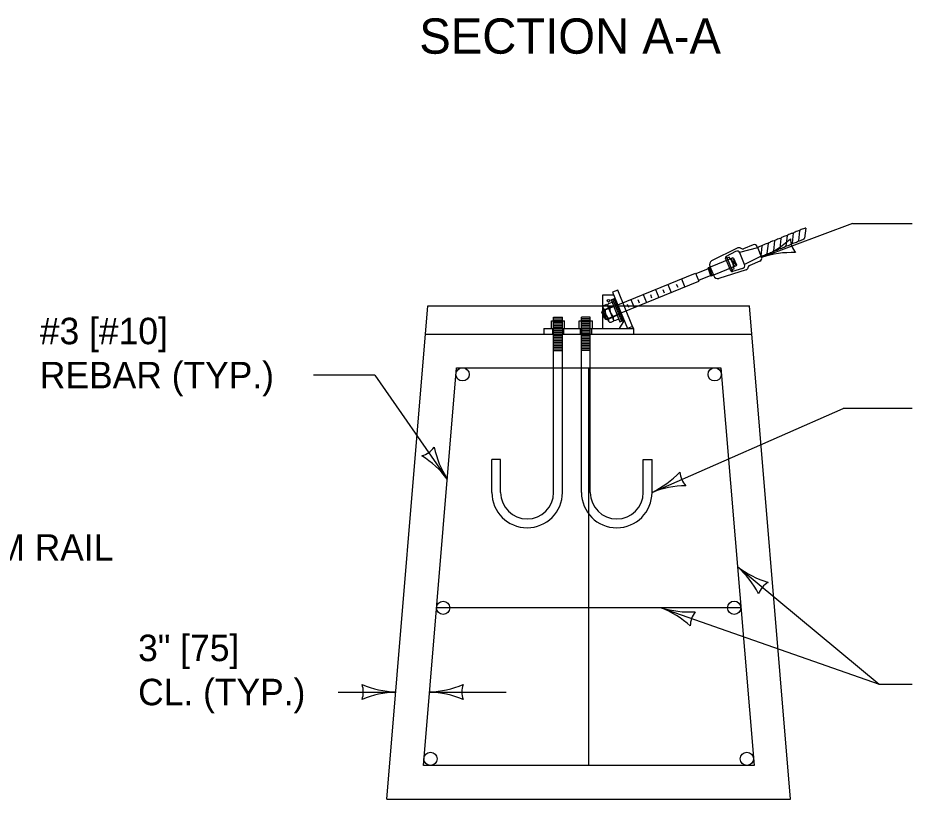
# Model space of a CAD drawing. Extents: x 49991.4 to 50021, y 49987.6 to 50011.4.
# Drawn here: x 50005.459 to 50007.485, y 49991.289 to 49993.059 of the extents above; entities that cross this region are included whole.
import ezdxf

# ---------------------------------------------------------------- set-up
doc = ezdxf.new("R2010")
doc.units = 0
for name, color, linetype in [('Level 1', 7, 'Continuous'), ('Level 2', 7, 'Continuous'), ('Level 3', 7, 'Continuous'), ('Level 4', 7, 'Continuous'), ('Level 7', 7, 'Continuous')]:
    doc.layers.add(name, color=color, linetype=linetype)

msp = doc.modelspace()

# ---------------------------------------------------------------- linework, layer by layer
at = {"layer": 'Level 1'}
for p, q in [((50007.2437, 49992.5827), (50007.2413, 49992.56)), ((50007.1874, 49992.5595), (50007.1849, 49992.537)), ((50007.1874, 49992.5595), (50007.1875, 49992.5596)), ((50007.2016, 49992.5653), (50007.199, 49992.5427)), ((50007.2157, 49992.5711), (50007.2131, 49992.5485)), ((50007.2298, 49992.5768), (50007.2272, 49992.5542)), ((50007.0888, 49992.5374), (50007.0305, 49992.5085)), ((50007.0955, 49992.5379), (50007.1, 49992.536)), ((50007.125, 49992.545), (50007.1025, 49992.5358)), ((50007.1337, 49992.5413), (50007.1437, 49992.5166)), ((50007.1426, 49992.5195), (50007.1451, 49992.5425)), ((50007.1567, 49992.5255), (50007.1592, 49992.5482)), ((50007.1733, 49992.5539), (50007.1708, 49992.5312)), ((50007.0849, 49992.5299), (50007.0639, 49992.5187)), ((50007.0707, 49992.517), (50007.0653, 49992.5148)), ((50007.105, 49992.5002), (50007.0943, 49992.5266)), ((50007.0647, 49992.5162), (50007.0622, 49992.5152)), ((50007.0738, 49992.4864), (50007.0624, 49992.5145)), ((50007.0647, 49992.5162), (50007.077, 49992.4868)), ((50007.0786, 49992.5156), (50007.0732, 49992.5134)), ((50007.0749, 49992.5141), (50007.0826, 49992.496)), ((50007.0784, 49992.5155), (50007.0861, 49992.4974)), ((50007.0802, 49992.5149), (50007.0786, 49992.5156)), ((50007.0786, 49992.5092), (50007.0817, 49992.502)), ((50007.0802, 49992.5149), (50007.0867, 49992.4996)), ((50007.0863, 49992.4975), (50007.0809, 49992.4953)), ((50007.0867, 49992.4996), (50007.0863, 49992.4975)), ((50007.1401, 49992.5079), (50007.1175, 49992.4984)), ((50006.8179, 49992.4091), (50006.9939, 49992.4808)), ((50006.9939, 49992.4808), (50007.0015, 49992.4623)), ((50007.0226, 49992.4908), (50006.9946, 49992.4791)), ((50007.0272, 49992.4947), (50007.0219, 49992.4925)), ((50007.0219, 49992.4925), (50007.0291, 49992.4742)), ((50007.0319, 49992.4753), (50007.0247, 49992.4937)), ((50007.0258, 49992.4866), (50007.0281, 49992.481)), ((50007.0266, 49992.4962), (50007.0355, 49992.4746)), ((50007.0288, 49992.4878), (50007.0311, 49992.4822)), ((50007.0347, 49992.4765), (50007.0291, 49992.4742)), ((50007.1085, 49992.4882), (50007.0468, 49992.4686)), ((50007.077, 49992.4868), (50007.0742, 49992.4856)), ((50007.0818, 49992.4904), (50007.0764, 49992.4882)), ((50007.1007, 49992.4912), (50007.0779, 49992.4845)), ((50007.1136, 49992.4949), (50007.1118, 49992.4906)), ((50006.8255, 49992.3905), (50007.0015, 49992.4623)), ((50006.9506, 49992.4559), (50006.9537, 49992.449)), ((50006.9621, 49992.4678), (50006.9696, 49992.4493)), ((50007.0287, 49992.4753), (50007.0008, 49992.4639)), ((50006.818, 49992.4426), (50006.8062, 49992.4378)), ((50006.8062, 49992.4378), (50006.8398, 49992.3554)), ((50006.8516, 49992.3602), (50006.818, 49992.4426)), ((50006.9037, 49992.444), (50006.9112, 49992.4255)), ((50006.9198, 49992.4437), (50006.9228, 49992.4364)), ((50006.9315, 49992.4553), (50006.9393, 49992.4369)), ((50006.7838, 49992.4314), (50006.8088, 49992.4314)), ((50006.7838, 49992.3953), (50006.7838, 49992.4314)), ((50006.8029, 49992.4203), (50006.8117, 49992.4244)), ((50006.8029, 49992.4203), (50006.8227, 49992.3707)), ((50006.806, 49992.4217), (50006.8262, 49992.372)), ((50006.8087, 49992.423), (50006.8293, 49992.3731)), ((50006.8478, 49992.4213), (50006.8554, 49992.4027)), ((50006.8637, 49992.4208), (50006.8668, 49992.4139)), ((50006.8756, 49992.4326), (50006.8831, 49992.414)), ((50006.8918, 49992.4323), (50006.8947, 49992.425)), ((50006.2946, 49991.2887), (50006.3877, 49992.4067)), ((50006.3877, 49992.4067), (50006.7855, 49992.4067)), ((50006.7821, 49992.3923), (50006.7832, 49992.3951)), ((50006.7832, 49992.3951), (50006.7869, 49992.3966)), ((50006.7915, 49992.3758), (50006.7838, 49992.3953)), ((50006.7971, 49992.3723), (50006.7846, 49992.4019)), ((50006.7871, 49992.4078), (50006.7935, 49992.4105)), ((50006.7906, 49992.3994), (50006.797, 49992.4021)), ((50006.7935, 49992.4105), (50006.8093, 49992.3724)), ((50006.7977, 49992.4122), (50006.805, 49992.4152)), ((50006.8012, 49992.4038), (50006.8083, 49992.4068)), ((50006.8394, 49992.4106), (50006.8421, 49992.4039)), ((50006.865, 49992.4067), (50007.1164, 49992.4067)), ((50007.2096, 49991.2887), (50007.1164, 49992.4067)), ((50006.6726, 49992.3808), (50006.6926, 49992.3808)), ((50006.6726, 49992.3554), (50006.6726, 49992.3808)), ((50006.6726, 49992.377), (50006.6926, 49992.377)), ((50006.6926, 49992.3554), (50006.6926, 49992.3808)), ((50006.7556, 49992.3808), (50006.7356, 49992.3808)), ((50006.7356, 49992.3554), (50006.7356, 49992.3808)), ((50006.7556, 49992.377), (50006.7356, 49992.377)), ((50006.7556, 49992.3554), (50006.7556, 49992.3808)), ((50006.7883, 49992.3771), (50006.7821, 49992.3923)), ((50006.7838, 49992.3554), (50006.7838, 49992.388)), ((50006.7887, 49992.3802), (50006.7843, 49992.3899)), ((50006.7913, 49992.381), (50006.7875, 49992.3909)), ((50006.7883, 49992.3771), (50006.7915, 49992.3758)), ((50006.7915, 49992.3758), (50006.795, 49992.3773)), ((50006.7996, 49992.3782), (50006.8058, 49992.3808)), ((50006.81, 49992.3825), (50006.8169, 49992.3854)), ((50006.8135, 49992.3741), (50006.8203, 49992.3769)), ((50006.6506, 49992.3554), (50006.8536, 49992.3554)), ((50006.6506, 49992.3554), (50006.6506, 49992.3427)), ((50006.6676, 49992.3554), (50006.6676, 49992.3724)), ((50006.6676, 49992.3724), (50006.6976, 49992.3724)), ((50006.6726, 49992.3733), (50006.6926, 49992.3733)), ((50006.6976, 49992.3554), (50006.6976, 49992.3724)), ((50006.7306, 49992.3554), (50006.7306, 49992.3724)), ((50006.7306, 49992.3724), (50006.7606, 49992.3724)), ((50006.7556, 49992.3733), (50006.7356, 49992.3733)), ((50006.7606, 49992.3554), (50006.7606, 49992.3724)), ((50006.803, 49992.3698), (50006.8093, 49992.3724)), ((50006.8218, 49992.3554), (50006.8327, 49992.373)), ((50006.8227, 49992.3707), (50006.8322, 49992.3742)), ((50006.8516, 49992.3602), (50006.8398, 49992.3554)), ((50006.8536, 49992.3554), (50006.8536, 49992.3427)), ((50006.3824, 49992.3427), (50007.1217, 49992.3427)), ((50006.6506, 49992.3427), (50006.8536, 49992.3427)), ((50006.6726, 49991.9838), (50006.6726, 49992.3427)), ((50006.6726, 49992.3395), (50006.6926, 49992.3395)), ((50006.6726, 49992.3358), (50006.6926, 49992.3358)), ((50006.6926, 49991.9838), (50006.6926, 49992.3427)), ((50006.7356, 49991.9838), (50006.7356, 49992.3427)), ((50006.7556, 49992.3395), (50006.7356, 49992.3395)), ((50006.7556, 49992.3358), (50006.7356, 49992.3358)), ((50006.7556, 49991.9838), (50006.7556, 49992.3427)), ((50006.6726, 49992.332), (50006.6926, 49992.332)), ((50006.6726, 49992.3283), (50006.6926, 49992.3283)), ((50006.6726, 49992.3245), (50006.6926, 49992.3245)), ((50006.6726, 49992.3208), (50006.6926, 49992.3208)), ((50006.6726, 49992.317), (50006.6926, 49992.317)), ((50006.7556, 49992.332), (50006.7356, 49992.332)), ((50006.7556, 49992.3283), (50006.7356, 49992.3283)), ((50006.7556, 49992.3245), (50006.7356, 49992.3245)), ((50006.7556, 49992.3208), (50006.7356, 49992.3208)), ((50006.7556, 49992.317), (50006.7356, 49992.317)), ((50006.6726, 49992.3133), (50006.6926, 49992.3133)), ((50006.6726, 49992.3095), (50006.6926, 49992.3095)), ((50006.6726, 49992.3058), (50006.6926, 49992.3058)), ((50006.7556, 49992.3133), (50006.7356, 49992.3133)), ((50006.7556, 49992.3095), (50006.7356, 49992.3095)), ((50006.7556, 49992.3058), (50006.7356, 49992.3058)), ((50006.3774, 49991.3649), (50006.4525, 49992.2664)), ((50006.4525, 49992.2664), (50007.0516, 49992.2664)), ((50006.7521, 49991.3649), (50006.7521, 49992.2664)), ((50007.0516, 49992.2664), (50007.1267, 49991.3649)), ((50006.5326, 49991.9838), (50006.5326, 49992.0588)), ((50006.5526, 49992.0588), (50006.5326, 49992.0588)), ((50006.5526, 49991.9838), (50006.5526, 49992.0588)), ((50006.8756, 49991.9838), (50006.8756, 49992.0588)), ((50006.8756, 49992.0588), (50006.8956, 49992.0588)), ((50006.8956, 49991.9838), (50006.8956, 49992.0588)), ((50007.0969, 49991.7224), (50006.4072, 49991.7224)), ((50007.1267, 49991.3649), (50006.3774, 49991.3649)), ((50006.2946, 49991.2887), (50007.2096, 49991.2887))]:
    msp.add_line(p, q, dxfattribs=at)
msp.add_circle((50006.7968, 49992.4184), 0.003, dxfattribs=at)
for centre, radius, start, end in [((50007.0926, 49992.5296), 0.00869, 71.024, 116.4266), ((50007.1277, 49992.5394), 0.00626, 18.1575, 116.1851), ((50007.0655, 49992.5157), 0.00334, 118.148, 202.0396), ((50007.0259, 49992.4826), 0.0564, 7.926, 37.5049), ((50007.0881, 49992.524), 0.00669, 22.1713, 118.0774), ((50007.1016, 49992.5435), 0.00767, 257.4447, 276.394), ((50007.1379, 49992.5139), 0.00643, 290.3941, 24.6183), ((50007.0359, 49992.5), 0.0101, 122.4373, 201.9486), ((50007.0988, 49992.4976), 0.00669, 286.138, 22.1713), ((50007.1194, 49992.4925), 0.00621, 107.6118, 157.3837), ((50007.0768, 49992.4876), 0.00328, 202.6255, 288.115), ((50007.1069, 49992.494), 0.00601, 285.8571, 325.6054), ((50007.0446, 49992.4781), 0.00976, 200.9643, 282.5696), ((50006.7889, 49992.4036), 0.00454, 112.4468, 292.444), ((50006.8095, 49992.3946), 0.02, 166.3862, 237.2279), ((50006.7995, 49992.408), 0.00454, 112.4468, 292.444), ((50006.8199, 49992.3991), 0.02, 166.8789, 237.8792), ((50006.8013, 49992.374), 0.00454, 112.4468, 292.444), ((50006.8117, 49992.3783), 0.00454, 112.4468, 292.444), ((50006.8464, 49992.3552), 0.0072, 1.022, 43.358), ((50006.6126, 49991.9838), 0.08, 180, 0), ((50006.6126, 49991.9838), 0.06, 180, 0), ((50006.8156, 49991.9838), 0.08, 180, 0), ((50006.8156, 49991.9838), 0.06, 180, 0)]:
    msp.add_arc(centre, radius, start, end, dxfattribs=at)
for centre, major_axis, ratio, start_param, end_param in [((50007.2227, 49992.5739), (-0.00705, -0.00287), 0.155406, 3.141593, 6.283185), ((50007.2368, 49992.5797), (-0.00705, -0.00287), 0.155406, 3.290169, 6.283185), ((50007.1804, 49992.5566), (-0.00705, -0.00287), 0.155406, 3.141593, 6.219359), ((50007.1945, 49992.5625), (-0.00705, -0.00287), 0.155406, 3.141593, 6.283185), ((50007.2086, 49992.5682), (-0.00705, -0.00287), 0.155406, 3.141593, 6.283185), ((50007.2342, 49992.5571), (0.00705, 0.00287), 0.155406, 3.141593, 6.283185), ((50007.14, 49992.5403), (0.00515, 0.00214), 0.140692, 0, 2.948999), ((50007.1522, 49992.5454), (-0.00705, -0.00287), 0.155406, 3.141593, 6.283185), ((50007.1663, 49992.5511), (-0.00705, -0.00287), 0.155406, 3.096503, 6.283185), ((50007.1778, 49992.5341), (0.00705, 0.00287), 0.155406, 3.141593, 6.283185), ((50007.1919, 49992.5398), (0.00705, 0.00287), 0.155406, 3.141593, 6.283185), ((50007.206, 49992.5456), (0.00705, 0.00287), 0.155406, 3.141593, 6.283185), ((50007.2201, 49992.5513), (0.00705, 0.00287), 0.155406, 3.141593, 6.283185), ((50007.1496, 49992.5226), (0.00705, 0.00287), 0.155406, 3.141593, 6.283185), ((50007.1637, 49992.5284), (0.00705, 0.00287), 0.155406, 3.141593, 6.283185)]:
    msp.add_ellipse(centre, major_axis=major_axis, ratio=ratio, start_param=start_param, end_param=end_param, dxfattribs=at)
at = {"layer": 'Level 3'}
for p, q in [((50007.3499, 49992.5932), (50007.1437, 49992.5166)), ((50007.3499, 49992.5932), (50007.4849, 49992.5932)), ((50006.2673, 49992.2497), (50006.1289, 49992.2497)), ((50006.2673, 49992.2497), (50006.4315, 49992.0141)), ((50006.8956, 49991.9838), (50007.3286, 49992.1739)), ((50007.4849, 49992.1739), (50007.3286, 49992.1739)), ((50007.0891, 49991.8157), (50007.4099, 49991.5492)), ((50006.916, 49991.7224), (50007.4099, 49991.5492)), ((50007.4099, 49991.5492), (50007.4849, 49991.5492)), ((50006.1843, 49991.5314), (50006.3148, 49991.5314)), ((50006.3913, 49991.5314), (50006.5647, 49991.5314))]:
    msp.add_line(p, q, dxfattribs=at)
for centre, radius, start, end in [((50007.0519, 49992.7308), 0.233, 293.2117, 312.4616), ((50007.2639, 49992.5613), 0.0548, 182.5232, 218.2456), ((50007.2125, 49992.3052), 0.2223, 87.8404, 108.0239), ((50006.3582, 49992.1193), 0.0548, 287.0236, 322.746), ((50006.629, 49992.1377), 0.233, 192.8076, 212.0575), ((50006.2545, 49991.8795), 0.2223, 37.2453, 57.4288), ((50006.7915, 49992.1922), 0.233, 296.5314, 315.7812), ((50007.013, 49992.0353), 0.0548, 185.8429, 221.5653), ((50006.9765, 49991.7767), 0.2223, 91.1601, 111.3436), ((50006.9402, 49991.6506), 0.2223, 27.7464, 47.9299), ((50007.229, 49992.002), 0.233, 233.1177, 252.3676), ((50007.1878, 49991.7338), 0.0548, 122.4292, 158.1516), ((50006.8339, 49991.5158), 0.2223, 48.1348, 68.3183), ((50006.9822, 49991.9458), 0.233, 253.5061, 272.756), ((50007.037, 49991.68), 0.0548, 142.8176, 178.54), ((50006.3239, 49991.7536), 0.2223, 247.456, 267.6395), ((50006.1866, 49991.5314), 0.0548, 342.1388, 17.8612), ((50006.3798, 49991.7642), 0.233, 272.8273, 292.0772), ((50006.5195, 49991.5314), 0.0548, 162.1388, 197.8612), ((50006.3263, 49991.2987), 0.233, 92.8273, 112.0772), ((50006.3821, 49991.3093), 0.2223, 67.456, 87.6395)]:
    msp.add_arc(centre, radius, start, end, dxfattribs=at)
at = {"layer": 'Level 4'}
for p, q in [((50007.1349, 49992.5384), (50007.0939, 49992.5273)), ((50007.1426, 49992.5194), (50007.105, 49992.5003)), ((50007.0732, 49992.5134), (50007.0272, 49992.4947)), ((50007.0809, 49992.4953), (50007.0347, 49992.4765)), ((50006.7838, 49992.388), (50006.7838, 49992.3953)), ((50006.7855, 49992.4067), (50006.865, 49992.4067)), ((50006.7869, 49992.3966), (50006.8179, 49992.4091)), ((50006.795, 49992.3773), (50006.8255, 49992.3905)), ((50006.6701, 49992.3554), (50006.6701, 49992.3427)), ((50006.6726, 49992.3695), (50006.6926, 49992.3695)), ((50006.6726, 49992.3658), (50006.6926, 49992.3658)), ((50006.6726, 49992.362), (50006.6926, 49992.362)), ((50006.6726, 49992.3583), (50006.6926, 49992.3583)), ((50006.6726, 49992.3427), (50006.6726, 49992.3554)), ((50006.6726, 49992.3545), (50006.6926, 49992.3545)), ((50006.6926, 49992.3554), (50006.6926, 49992.3427)), ((50006.6951, 49992.3554), (50006.6951, 49992.3427)), ((50006.7331, 49992.3554), (50006.7331, 49992.3427)), ((50006.7556, 49992.3695), (50006.7356, 49992.3695)), ((50006.7556, 49992.3658), (50006.7356, 49992.3658)), ((50006.7556, 49992.362), (50006.7356, 49992.362)), ((50006.7556, 49992.3583), (50006.7356, 49992.3583)), ((50006.7356, 49992.3554), (50006.7356, 49992.3427)), ((50006.7556, 49992.3545), (50006.7356, 49992.3545)), ((50006.7556, 49992.3427), (50006.7556, 49992.3554)), ((50006.7581, 49992.3554), (50006.7581, 49992.3427)), ((50006.6726, 49992.3508), (50006.6926, 49992.3508)), ((50006.6726, 49992.347), (50006.6926, 49992.347)), ((50006.6726, 49992.3433), (50006.6926, 49992.3433)), ((50006.7556, 49992.3508), (50006.7356, 49992.3508)), ((50006.7556, 49992.347), (50006.7356, 49992.347)), ((50006.7556, 49992.3433), (50006.7356, 49992.3433))]:
    msp.add_line(p, q, dxfattribs=at)
at = {"layer": 'Level 7'}
for centre in [(50006.4663, 49992.2514), (50007.0375, 49992.2514), (50006.4222, 49991.7223), (50007.0818, 49991.7224), (50006.3936, 49991.3799), (50007.1104, 49991.3799)]:
    msp.add_circle(centre, 0.015, dxfattribs=at)

# ---------------------------------------------------------------- texts
at = {"layer": 'Level 2'}
for s, height, p in [('SECTION A-A', 0.08, (50006.3682, 49992.9782)), ('#3 [#10] ', 0.06, (50005.5085, 49992.3197)), ('REBAR (TYP.)', 0.06, (50005.5085, 49992.2197)), ('BOX BEAM RAIL', 0.06, (50005.0553, 49991.829))]:
    msp.add_text(s, height=height, dxfattribs=at).set_placement(p)
for s, p in [('3" [75]', (50005.7312, 49991.6014)), ('CL. (TYP.)', (50005.7312, 49991.5014))]:
    msp.add_text(s, height=0.06, rotation=360, dxfattribs=at).set_placement(p)

doc.saveas('drawing.dxf')
